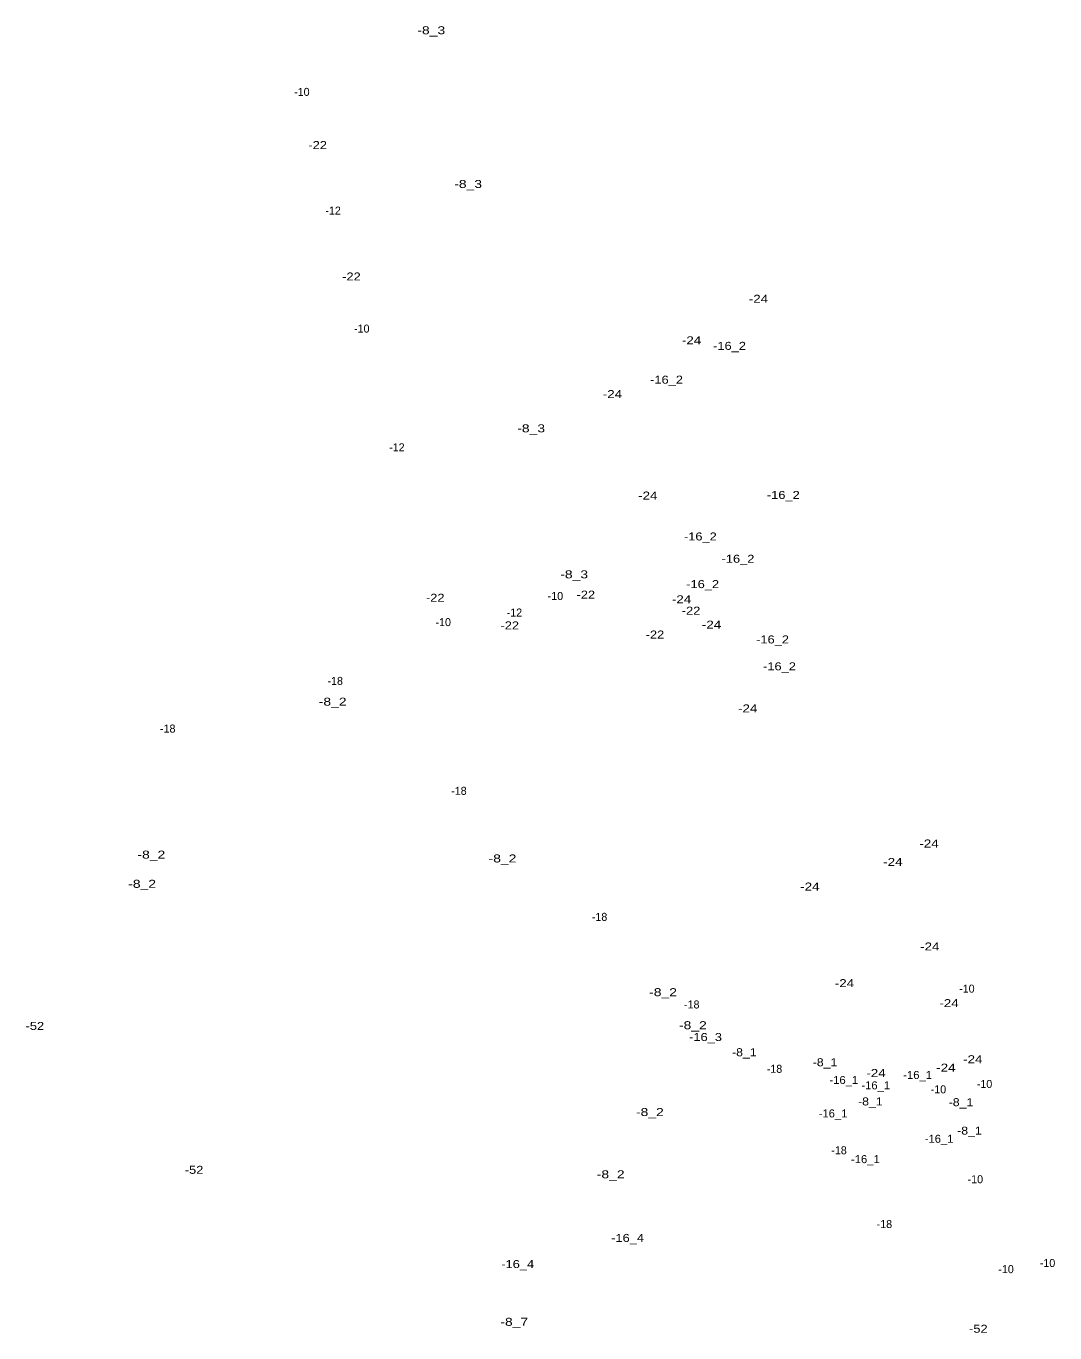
# Model space of a CAD drawing. Extents: x -663241 to -661169, y -1003538 to -1000899.
# Drawn here: x -661725 to -661211, y -1001552 to -1000899 of the extents above; entities that cross this region are included whole.
import ezdxf
from ezdxf.enums import TextEntityAlignment as Align

# ---------------------------------------------------------------- set-up
doc = ezdxf.new("R2010")
doc.units = 0
doc.header["$LTSCALE"] = 1.6
doc.layers.add('24', color=7, linetype='Continuous')

msp = doc.modelspace()

# ---------------------------------------------------------------- texts
at = {"layer": '24'}
for s, width, p in [('-8_3', 1.3, (-661522.62, -1000902.56)), ('-22', 1.2, (-661579.39, -1000959.96)), ('-8_3', 1.3, (-661504.179, -1000979.39)), ('-22', 1.2, (-661562.49, -1001025.65)), ('-24', 1.25, (-661359.09, -1001036.8)), ('-24', 1.25, (-661392.5, -1001057.55)), ('-16_2', 1.2, (-661373.53, -1001060.32)), ('-16_2', 1.2, (-661405.02, -1001077.23)), ('-24', 1.25, (-661432.06, -1001084.44)), ('-8_3', 1.3, (-661472.689, -1001101.55)), ('-24', 1.25, (-661414.39, -1001135.15)), ('-16_2', 1.2, (-661346.65, -1001134.85)), ('-16_2', 1.2, (-661388.12, -1001155.6)), ('-16_2', 1.2, (-661369.311, -1001166.74)), ('-8_3', 1.3, (-661451.189, -1001174.54)), ('-16_2', 1.2, (-661386.971, -1001179.41)), ('-22', 1.2, (-661520.63, -1001186.23)), ('-22', 1.2, (-661445.37, -1001184.69)), ('-24', 1.25, (-661397.5, -1001187.01)), ('-22', 1.2, (-661392.76, -1001192.71)), ('-22', 1.2, (-661483.38, -1001200.06)), ('-24', 1.25, (-661382.52, -1001199.68)), ('-22', 1.2, (-661410.81, -1001204.62)), ('-16_2', 1.2, (-661352.03, -1001207.07)), ('-16_2', 1.2, (-661348.571, -1001220.52)), ('-8_2', 1.3, (-661571.89, -1001238.18)), ('-24', 1.25, (-661364.47, -1001241.56)), ('-8_2', 1.3, (-661662.51, -1001314.63)), ('-24', 1.25, (-661273.84, -1001309.08)), ('-8_2', 1.3, (-661487.02, -1001316.55)), ('-24', 1.25, (-661291.89, -1001318.3)), ('-8_2', 1.3, (-661667.12, -1001329.23)), ('-24', 1.25, (-661333.37, -1001330.59)), ('-24', 1.25, (-661273.46, -1001360.56)), ('-24', 1.25, (-661316.09, -1001378.89)), ('-8_2', 1.3, (-661406.76, -1001383.4)), ('-24', 1.25, (-661263.86, -1001388.87)), ('-52', 1.2, (-661720.73, -1001400.28)), ('-8_2', 1.3, (-661391.86, -1001399.91)), ('-16_3', 1.2, (-661385.53, -1001405.81)), ('-8_1', 1.15, (-661366.14, -1001413.42)), ('-8_1', 1.15, (-661325.819, -1001418.42)), ('-24', 1.25, (-661251.96, -1001416.92)), ('-24', 1.25, (-661300.34, -1001423.83)), ('-16_1', 1.05, (-661279.541, -1001424.79)), ('-24', 1.25, (-661265.4, -1001421.14)), ('-16_1', 1.05, (-661316.41, -1001427.29)), ('-16_1', 1.05, (-661300.471, -1001429.98)), ('-8_1', 1.15, (-661303.16, -1001438.01)), ('-8_1', 1.15, (-661257.85, -1001438.39)), ('-8_2', 1.3, (-661413.36, -1001443.32)), ('-16_1', 1.05, (-661321.791, -1001444)), ('-16_1', 1.05, (-661268.791, -1001456.68)), ('-8_1', 1.15, (-661253.62, -1001452.61)), ('-16_1', 1.05, (-661305.66, -1001466.86)), ('-52', 1.2, (-661641.15, -1001472.2)), ('-8_2', 1.3, (-661432.949, -1001474.44)), ('-16_4', 1.2, (-661424.48, -1001506.24)), ('-16_4', 1.2, (-661479.4, -1001519.3)), ('-8_7', 1.3, (-661481.13, -1001548.18)), ('-52', 1.2, (-661249.18, -1001551.64))]:
    msp.add_text(s, height=4, dxfattribs=dict(at, width=width)).set_placement(p, align=Align.CENTER)
for s, p in [('-10', (-661587.28, -1000933.37)), ('-12', (-661571.671, -1000992.71)), ('-10', (-661557.331, -1001051.69)), ('-12', (-661539.791, -1001111.02)), ('-10', (-661460.561, -1001185.37)), ('-12', (-661481.041, -1001193.62)), ('-10', (-661516.63, -1001198.43)), ('-18', (-661570.611, -1001227.81)), ('-18', (-661654.321, -1001251.63)), ('-18', (-661508.78, -1001282.75)), ('-18', (-661438.5, -1001345.75)), ('-10', (-661254.921, -1001381.63)), ('-18', (-661392.421, -1001389.54)), ('-18', (-661351.071, -1001421.7)), ('-10', (-661269.13, -1001431.96)), ('-10', (-661246.091, -1001429.27)), ('-18', (-661318.811, -1001462.42)), ('-10', (-661250.691, -1001476.9)), ('-18', (-661296.15, -1001499.3)), ('-10', (-661235.331, -1001521.85)), ('-10', (-661214.601, -1001518.77))]:
    msp.add_text(s, height=4, dxfattribs=at).set_placement(p, align=Align.CENTER)

doc.saveas('drawing.dxf')
